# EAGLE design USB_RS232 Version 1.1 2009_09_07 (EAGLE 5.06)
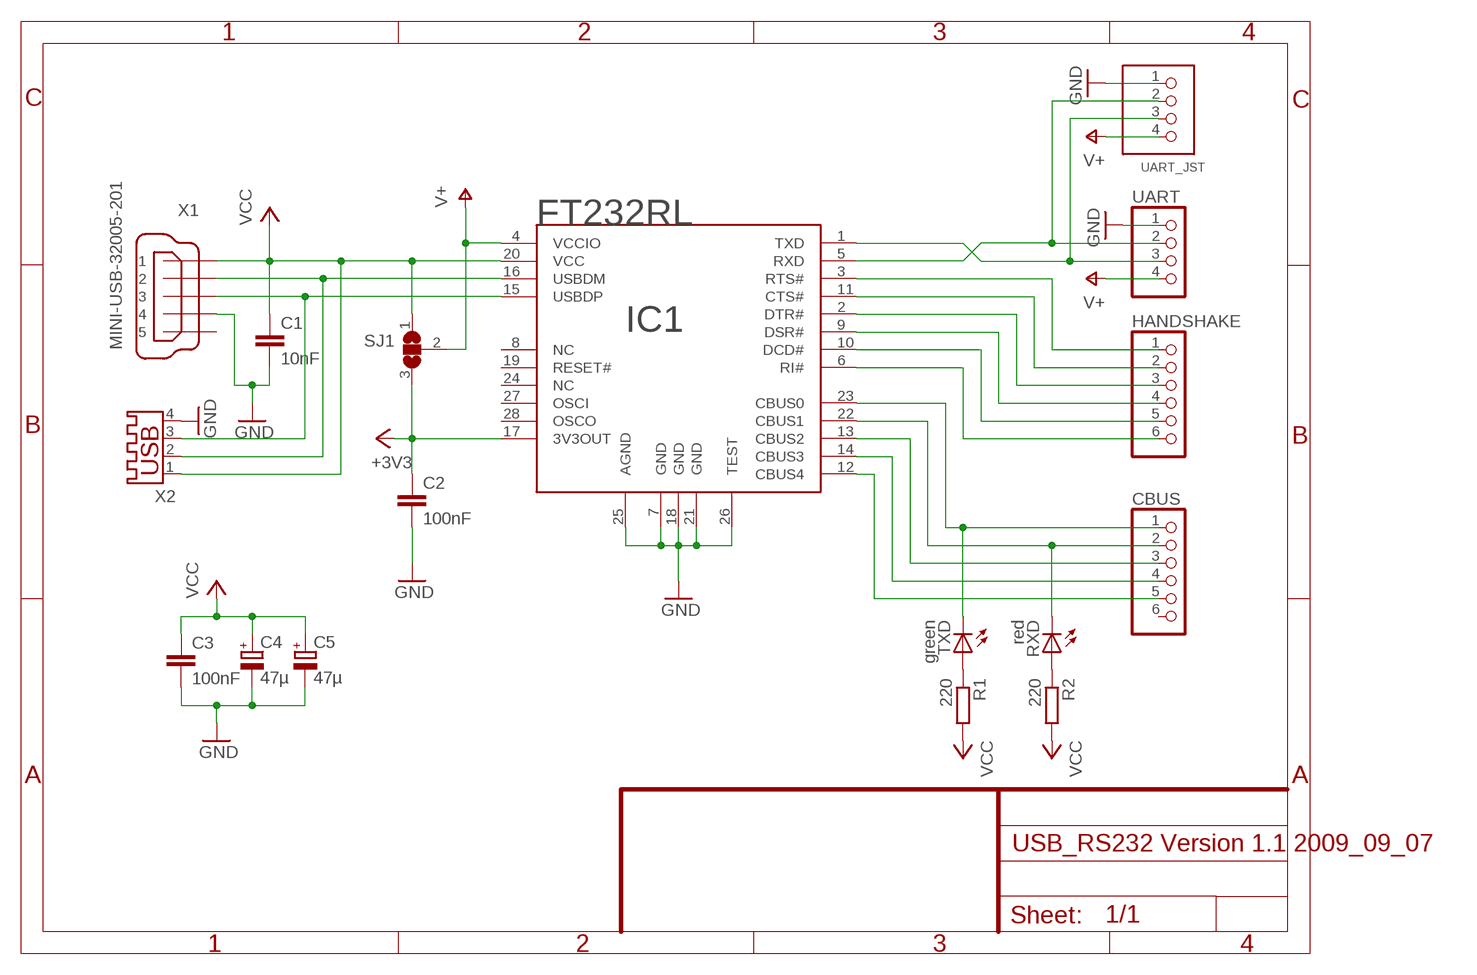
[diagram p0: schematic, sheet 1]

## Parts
C1  10nF  C-EUC0805  [C0805]
C2  100nF  C-EUC0805  [C0805]
C3  100nF  C-EUC0805  [C0805]
C4  47µ  CPOL-EU085CS-1AR  [085CS_1AR]
C5  47µ  CPOL-EU085CS-1AR  [085CS_1AR]
CBUS  PINHD-1X6  [1X06]
HANDSHAKE  PINHD-1X6  [1X06]
IC1  FT232RL  [SSOP28]
R1  220  R-EU_M0805  [M0805]
R2  220  R-EU_M0805  [M0805]
RXD  red  LEDSMT1206  [1206]
SJ1  SJ2W  [SJ_2]
TXD  green  LEDSMT1206  [1206]
UART  PINHD-1X4  [1X04]
UART_JST  4PINS  [S4B-ZR-3.4]
X1  MINI-USB-32005-201  [32005-201]
X2  USB-A003  [USB-A003]

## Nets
+3V3: C2.1 IC1.17(3V3OUT) SJ1.3
GND: C1.2 C2.2 C3.2 C4.- C5.- IC1.7(GND) IC1.18(GND) IC1.21(GND) IC1.25(AGND) IC1.26(TEST) UART.1 UART_JST.1 X1.4 X2.4
N$1: IC1.16(USBDM) X1.2 X2.2
N$2: IC1.15(USBDP) X1.3 X2.3
N$4: IC1.1(TXD) UART.3 UART_JST.3
N$5: HANDSHAKE.1 IC1.3(RTS#)
N$6: IC1.5(RXD) UART.2 UART_JST.2
N$7: HANDSHAKE.2 IC1.11(CTS#)
N$8: HANDSHAKE.3 IC1.2(DTR#)
N$9: R1.1 TXD.A
N$10: HANDSHAKE.4 IC1.9(DSR#)
N$11: HANDSHAKE.5 IC1.10(DCD#)
N$12: CBUS.1 IC1.23(CBUS0) TXD.C
N$13: CBUS.2 IC1.22(CBUS1) RXD.C
N$14: CBUS.3 IC1.13(CBUS2)
N$15: CBUS.4 IC1.14(CBUS3)
N$16: CBUS.5 IC1.12(CBUS4)
N$17: HANDSHAKE.6 IC1.6(RI#)
N$18: R2.1 RXD.A
V+: IC1.4(VCCIO) SJ1.2 UART.4 UART_JST.4
VCC: C1.1 C3.1 C4.+ C5.+ IC1.20(VCC) R1.2 R2.2 SJ1.1 X1.1 X2.1
Unconnected: CBUS.6 IC1.8(NC) IC1.19(RESET#) IC1.24(NC) IC1.27(OSCI) IC1.28(OSCO) X1.5

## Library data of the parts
C1-C3 = rcl:C-EU: CAPACITOR, European symbol
C4 C5 = rcl:CPOL-EU: POLARIZED CAPACITOR, European symbol
CBUS HANDSHAKE = pinheadRound:PINHD-1X6: PIN HEADER
IC1 = FTDI:FT232RL
R1 R2 = rcl:R-EU_: RESISTOR, European symbol
RXD TXD = led:LED: LED
SJ1 = jumper:SJ2W: SMD solder JUMPER
UART = pinheadRound:PINHD-1X4: PIN HEADER
UART_JST = rcos:4PIN
X1 = con-cypressindustries:MINI-USB-: MINI USB-B Conector Source: www.cypressindustries.com
X2 = con-yamaichi:USB-A003: USB connector

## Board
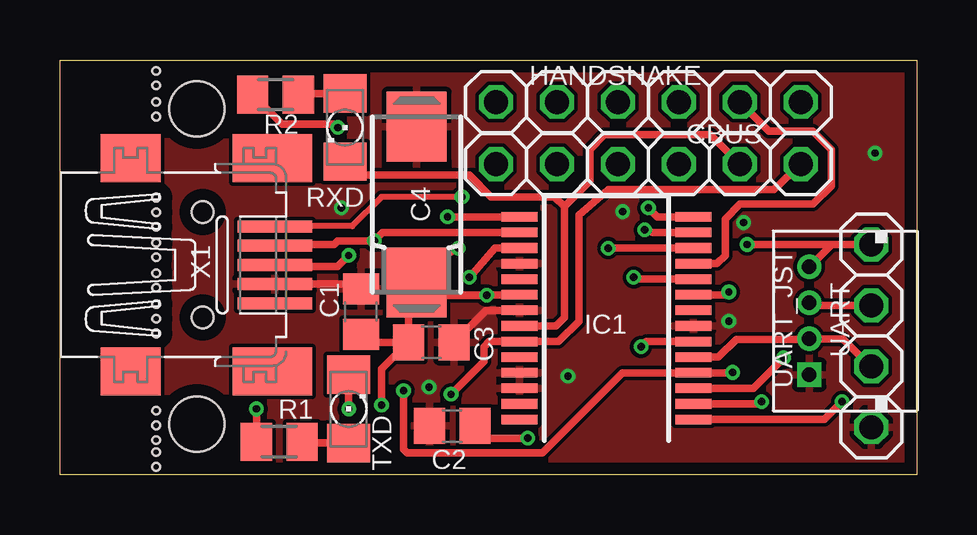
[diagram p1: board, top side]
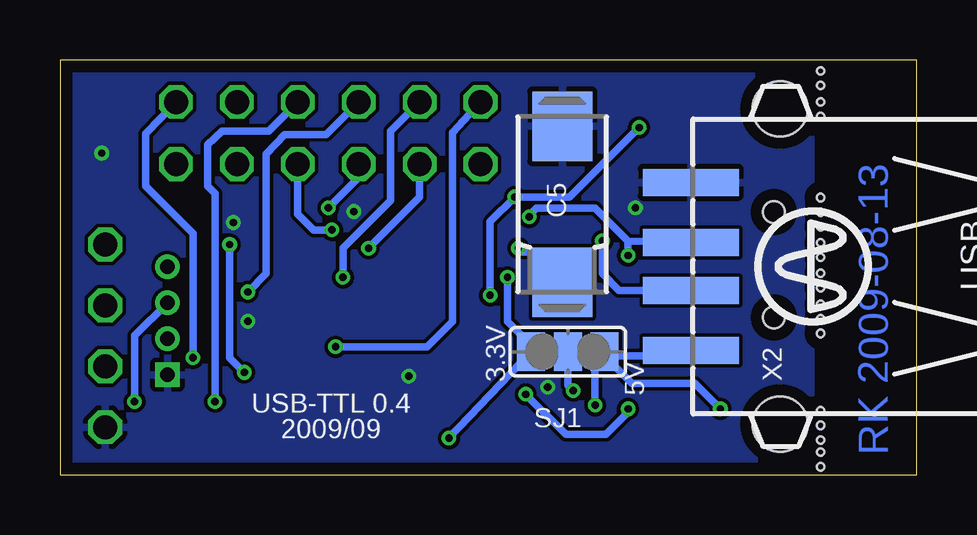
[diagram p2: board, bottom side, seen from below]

Size 35.72 x 17.3 mm. Coordinates in mm from the lower left corner, seen from the top.
Outline: 0,17.3 35.72,17.3 35.72,0 0,0 0,17.3
Copper layers (1*16): Top 0.035mm / dielectric 1.5mm / Bottom 0.035mm
Design rules "PCB-POOL": minimum track width 6mil, minimum drill 12mil, track to track 6mil, track to pad 6mil, pad to pad 6mil, via to via 6mil, smd to smd 6mil, copper to edge 20mil, drill to drill 8mil, minimum pad ring 8mil, minimum via ring 6mil, stop-mask expansion 3mil, vias tented up to drill 0mil, thermal gap 8mil
Holes 0.3 mm at 4.01,16.84 4.01,15.54 4.01,10.34 4.01,9.07 4.01,7.8 4.01,5.89 4.01,1.45 4.01,0.33 4.01,0.94 4.01,2.06 4.01,2.67 4.01,6.5 4.01,7.11 4.01,8.41 4.01,9.68 4.01,10.95 4.01,11.56 4.01,16.23 4.01,14.94

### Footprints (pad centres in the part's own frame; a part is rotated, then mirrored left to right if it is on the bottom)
C0805 = smd 1.3 x 1.5: 1 -0.95,0; 2 0.95,0
085CS_1AR = smd 2.9 x 2.5: + 3.25,0; - -3.25,0
1X06 = drill 1 octagon: 1 -6.35,0; 2 -3.81,0; 3 -1.27,0; 4 1.27,0; 5 3.81,0; 6 6.35,0
SSOP28 = smd 0.4 x 1.5: 1 -4.225,-3.625; 2 -3.575,-3.625; 3 -2.925,-3.625; 4 -2.275,-3.625; 5 -1.625,-3.625; 6 -0.975,-3.625; 7 -0.325,-3.625; 8 0.325,-3.625; 9 0.975,-3.625; 10 1.625,-3.625; 11 2.275,-3.625; 12 2.925,-3.625; 13 3.575,-3.625; 14 4.225,-3.625; 15 4.225,3.625; 16 3.575,3.625; 17 2.925,3.625; 18 2.275,3.625; 19 1.625,3.625; 20 0.975,3.625; 21 0.325,3.625; 22 -0.325,3.625; 23 -0.975,3.625; 24 -1.625,3.625; 25 -2.275,3.625; 26 -2.925,3.625; 27 -3.575,3.625; 28 -4.225,3.625
M0805 = smd 1.3 x 1.6: 1 -0.95,0; 2 0.95,0
1206 = smd 1.6 x 1.803: A -1.422,0; C 1.422,0
SJ_2 = smd 1.168 x 1.6: 1 -1.524,0; 2 0,0; 3 1.524,0
1X04 = drill 1 octagon: 1 -3.81,0; 2 -1.27,0; 3 1.27,0; 4 3.81,0
S4B-ZR-3.4 = drill 0.6 square: 1 2.23,0 | drill 0.6 round: 2 0.73,0; 3 -0.77,0; 4 -2.27,0
32005-201 = smd 3.1 x 0.5: 1 3,1.6; 2 3,0.8; 3 3,0; 4 3,-0.8; 5 3,-1.6 | smd 2.5 x 2: M1 -3,-4.45; M2 -3,4.45 | smd 3.3 x 2: M3 2.9,4.45; M4 2.9,-4.45 | hole 0.9: 0,2.2; 0,-2.2
USB-A003 = smd 1.12 x 4: 1 -3.5,14; 2 -1,14; 3 1,14; 4 3.5,14 | hole 2.3: -6.57,10.28; 6.57,10.28

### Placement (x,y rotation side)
C1  12.54,6.79 90 top
C2  16.35,2.03 180 top
C3  15.48,5.52 0 top
C4  14.87,11.27 270 top
C5  14.78,11.28 270 bottom
CBUS  24.53,12.95 180 top
HANDSHAKE  24.53,15.54 180 top
IC1  22.78,6.53 90 top
R1  9.14,1.37 180 top
R2  8.99,15.85 180 top
RXD  11.88,14.48 270 top
SJ1  14.55,5.13 180 bottom
TXD  12.03,2.74 90 top
UART  33.83,5.79 90 top
UART_JST  31.24,6.4 270 top
X1  5.95,8.75 0 top
X2  -4.58,8.69 90 bottom

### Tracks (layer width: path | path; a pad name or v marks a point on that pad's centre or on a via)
+3V3  (via drill 0.3)
  Top 0.305: C2.1 17.66,1.52 v19.5,1.52 | v17.06,8.23 18.13,9.45 IC1.17
  Bottom 0.305: v19.5,1.52 19.53,1.52 SJ1.3 16.07,5.41 17.06,6.4 v17.06,8.23
GND  (via drill 0.3)
  Top 0.305: C1.2 12.49,7.64 12.49,7.95 X1.4 | IC1.21 17.75,6.85 C3.2
  Top 0.406: IC1.25 19.29,4.25
  other vias: 21.18,4.11 15.39,3.66 11.73,11.13 33.98,13.41 27.88,6.4 23.46,10.97 28.49,10.52
  pour Bottom: 4.41,17.53 35.96,17.37 35.96,-0.15 4.41,0
  pour Top: 4.41,17.53 35.96,17.37 35.96,-0.15 4.41,0
N$1  (via drill 0.3)
  Top 0.254: 8.99,9.6 X1.2
  Top 0.305: IC1.16 13.45,10.1 v13.1,9.75 11.58,9.75 11.43,9.6 8.99,9.6
  Bottom 0.305: 10.6,7.69 10.97,7.62 | X2.2 12.41,7.69 13.1,8.38 v13.1,9.75
  Bottom 0.406: X2.2 10.6,7.69
N$2  (via drill 0.3)
  Top 0.254: X1.3 8.99,8.69
  Top 0.305: v16.16,10.75 IC1.15 | 8.99,8.69 11.58,8.69 v12.03,9.14
  Bottom 0.305: 12.03,9.75 8.62,9.69 | v12.03,9.14 12.03,9.75 | v16.16,10.75 16.15,10.82 15.84,11.13 13.41,11.13 12.03,9.75
  Bottom 0.406: 8.62,9.69 X2.3
N$4  (via drill 0.3)
  Top 0.305: UART_JST.3 31.35,7.06 UART.3 | IC1.1 31.86,2.3 v32.61,3.05
  Bottom 0.305: v32.61,3.05 32.61,5.8 UART_JST.3
N$5  (via drill 0.3)
  Top 0.305: IC1.3 28.9,3.6 v30.17,4.88
  Bottom 0.305: v30.17,4.88 30.17,10.06 32.15,12.04 32.15,14.22 HANDSHAKE.1
N$6
  Top 0.305: 33.83,4.42 UART.2 33.78,4.52 32.63,5.67 UART_JST.2 31.21,5.64 28.19,5.64 27.45,4.9 IC1.5
N$7
  Top 0.305: IC1.11 27.39,8.8 27.73,9.14 27.73,10.67 28.34,11.28 31.39,11.28 32.15,12.04 32.15,13.56 31.39,14.33 29.56,14.33 HANDSHAKE.2
N$8  (via drill 0.3)
  Top 0.305: IC1.2 29.31,2.95 v29.26,3.05
  Bottom 0.305: v29.26,3.05 29.26,11.74 29.56,12.04 29.56,13.77 28.95,14.33 27.02,14.33 HANDSHAKE.3
N$9
  Top 0.305: R1.1 10.14,1.32 TXD.A
N$10  (via drill 0.3)
  Top 0.305: v27.88,7.62 27.85,7.5 IC1.9
  Bottom 0.305: HANDSHAKE.4 24.63,14.17 26.36,14.17 27.12,13.36 27.12,8.38 v27.88,7.62
N$11  (via drill 0.3)
  Top 0.305: v23.92,8.23 24,8.15 IC1.10
  Bottom 0.305: HANDSHAKE.5 21.94,14.33 21.94,11.43 23.92,9.45 v23.92,8.23
N$12  (via drill 0.3)
  Top 0.305: CBUS.1 29.76,11.89 22.86,11.89 21.64,10.82 21.64,6.4 20.79,5.55 IC1.23 17.89,5.55 17.67,5.33 17.67,4.72 v16.3,3.35 | v12.03,2.74 TXD.C
  Bottom 0.305: v16.3,3.35 14.63,1.68 12.95,1.68 12.03,2.59 v12.03,2.74
N$13
  Top 0.305: IC1.22 20.68,6.2 21.03,6.55 21.03,11.18 | 21.03,11.18 22.09,12.24 22.09,13.56 22.7,14.17 27.12,14.17 CBUS.2 | 21.03,11.18 20.62,11.58 17.98,11.58 17.06,12.5 12.44,12.5 RXD.C 11.88,12.95
N$14  (via drill 0.3)
  Top 0.305: v24.38,10.21 24.73,10.1 IC1.13
  Bottom 0.305: CBUS.3 25.8,10.87 25.14,10.21 v24.38,10.21
N$15  (via drill 0.3)
  Top 0.305: v24.53,11.13 24.9,10.75 IC1.14
  Bottom 0.305: CBUS.4 23.26,12.4 v24.53,11.13
N$16  (via drill 0.3)
  Top 0.305: v22.86,9.45 23.16,9.45 IC1.12
  Bottom 0.305: v22.86,9.45 20.72,11.58 CBUS.5
N$17  (via drill 0.3)
  Top 0.305: v24.23,5.33 24.45,5.55 IC1.6
  Bottom 0.305: HANDSHAKE.6 19.35,14.28 19.35,6.4 20.42,5.33 v24.23,5.33
N$18
  Top 0.305: R2.1 9.99,15.9 RXD.A
V+  (via drill 0.3)
  Top 0.305: v28.65,9.6 UART.4 32.17,9.6 UART_JST.4 | v28.04,4.27 28.02,4.25 IC1.4 23.45,4.25 20.11,0.91 14.47,0.91 14.32,1.07 v14.32,3.51
  Bottom 0.305: v28.04,4.27 28.65,4.88 v28.65,9.6 | v14.32,3.51 14.55,3.73 SJ1.2
VCC  (via drill 0.3)
  Top 0.254: 15.69,6.95 14.65,6.97 | X1.1 8.99,10.36 12.19,10.36 13.41,11.58 v16.76,11.58
  Top 0.305: 15.16,7.48 v17.79,7.48 | 15.18,7.5 IC1.20 | C3.1 14.53,6.92 15.08,7.48 15.16,7.48 | C3.1 13.41,4.4 v13.41,2.9 | C1.1 12.54,5.52 C3.1 | R1.2 v8.19,2.74 | 15.16,7.48 14.87,7.47 C4.+ 14.87,8.93 15.24,9.3 16.3,9.3 16.45,9.45 v16.61,9.45 | R2.2 9.26,14.63 11.43,14.63 v11.58,14.48
  Top 0.406: 15.69,6.95 15.16,7.48 15.18,7.5
  Bottom 0.305: X2.1 9.58,5.03 9.6,5.03 9.67,4.95 13.03,4.95 | v17.79,7.48 17.79,10.55 v16.76,11.58 14.47,11.58 v11.58,14.48 | v13.41,2.9 13.41,4.88 13.33,4.95 13.03,4.95 | v16.61,9.45 16.45,9.3 15.24,9.3 14.78,8.84 C5.+ | v8.19,2.74 9.26,3.81 11.88,3.81 13.03,4.95 | 13.03,4.95 SJ1.1

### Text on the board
Bottom: RK 2009-08-13
bNames: 3.3V | 5V | USB-TTL 0.4 | 2009/09
bValues: 3.3V | 5V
